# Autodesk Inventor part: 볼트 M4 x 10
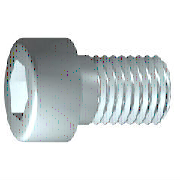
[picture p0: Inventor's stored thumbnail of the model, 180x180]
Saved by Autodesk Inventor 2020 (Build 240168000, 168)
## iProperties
IsCustomPart: 0
Created: 2012-02
Part Number: 볼트 M4 x 10
Material: 강철, 연강
Description: 6각 소켓 머리 캡 나사
Document SubType Name: Modeling
Standard: ISO 4762
Designer: mduedu
Standard Revision: Fourth edition 2004-03-01
Standards Organization: ISO
Language: ko-KR
Size Designation: M4 x 12
Categories: <MemberInstance><Categories><Category DisplayName="조임쇠" InternalName="e4da775c-781d-43d5-af7c-5136215cf5a6" Mnemonic="FSTN"><Category DisplayName="볼트" InternalN
Density: 7.75 g/cm^3
Appearance: 강철
Author: mduedu
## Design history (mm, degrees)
sketch "스케치1"
  geometry: L1 (-1, 0)-(10, 0); L2 (10, 0)-(10, 2); L3 (10, 2)-(1.75, 2); L4 (1.75, 2)-(1.32, 2); L5 (1.32, 2)-(0, 2); L6 (0, 2)-(0, 3.5); L7 (0, 3.5)-(-4, 3.5); L8 (-4, 3.5)-(-4, 1.732); L9 (-4, 1.732)-(-2, 1.732); L10 (-2, 1.732)-(-1, 0); L11 (-7.2, 0)-(15.2, 0) reference; L12 (0, -0.7)-(0, 4.2) reference; L13 (1.75, 2)-(0, 2)
  constraints: 22 end point, 6 parallel, 2 collinear, 2 perpendicular, 1 horizontal, 1 point on line
  dimensions: "d1" = 8.25 distance from line of L3.end L2 (= GEL); "d2" = 0.42952 distance of L4.end L3.end (computed from GAL); "d3" = 4 distance between parallel lines of L8 L6 (= KOH); "d4" = 2 distance of L8.end L9.end (= INTI); "d5" = 60 deg angle of L10 L1; "d6" = 4 diameter of L3 L1 (= GD); "d7" = 4 diameter of L5 L1 (= BDM); "d8" = 3.4641 diameter of L9 L1 (= 1.1547 x SW); "d9" = 7 diameter of L7 L1 (= KOD); "d26" = 10 distance between parallel lines of L12 L2 (= NLG)
revolve "본체" sketch "스케치1" stored, may be unused: angle "d10" = 90 deg
sketch "스케치2"
  geometry: L1 (0, -4.9)-(0, 4.9) reference; L2 (-4.9, 0)-(4.9, 0) reference; L3 (1.732, 0)-(0.866, -1.5); L4 (0.866, -1.5)-(-0.866, -1.5); L5 (-0.866, -1.5)-(-1.732, 0); L6 (-1.732, 0)-(-0.866, 1.5); L7 (-0.866, 1.5)-(0.866, 1.5); L8 (0.866, 1.5)-(1.732, 0); 2 further points
  constraints: 12 end point, 1 coincident, 1 horizontal alignment, 1 point on line, 12 other
extrude "슬롯" join sketch "스케치2" stored distance "d11" = 10; taper "d12" = 0 deg
workplane "Work Plane1"
fillet "Fillet2" dims "d30" = 0.1 (= R)
body "Solid1"
fillet "모깎기1" dims "d17" = 0.4 (= RR)
feature "스레드" dims "d13" = 8.25 (= GEL), "d14" = 0
chamfer "모따기1" distance "d15" = 0.42941 (= -0.5 x SPD + 0.5 x GD); stored, may be unused: second distance "d16" = 0.42941 (= GUL), angle "d27" = 45 deg
node "XZ 평면"
other parameters: "GD" = 4 [user parameter; used in 2 equation terms], "NLG" = 10 [user parameter; used in 1 equation term], "GEL" = 8.25 [user parameter; used in 2 equation terms], "KOD" = 7 [user parameter; used in 1 equation term], "KOH" = 4 [user parameter; used in 1 equation term], "INTI" = 2 [user parameter; used in 1 equation term], "GAL" = 0.42941 (= 0.61345 x PTC) [user parameter; used in 1 equation term], "GUL" = 0.42941 (= 0.61345 x PTC) [user parameter; used in 1 equation term], "BDM" = 4 (= NND) [user parameter; used in 1 equation term], "SW" = 3 [user parameter; used in 2 equation terms], "RR" = 0.4 [user parameter; used in 1 equation term], "SPD" = 3.14117 (= NND - 1.2269 x PTC) [user parameter; used in 1 equation term], "d19" = 0, "d28" = 0, "d29" = 0, "R" = 0.1 [user parameter; used in 1 equation term], "TOA" = 30 deg [user parameter], "GD1" = 3.14117 (= THREADDIA - 1.2269 x PTC) [user parameter], "THREADDIA" = 4 [user parameter; used in 1 equation term], "FAWI" = 45 deg [user parameter], "TPU" = 14.28571 (computed from PTC) [user parameter], "PTC" = 0.7 [user parameter; used in 5 equation terms], "NND" = 4 [user parameter; used in 2 equation terms], "E0" = 3.465 (= 1.155 x SW) [user parameter]
